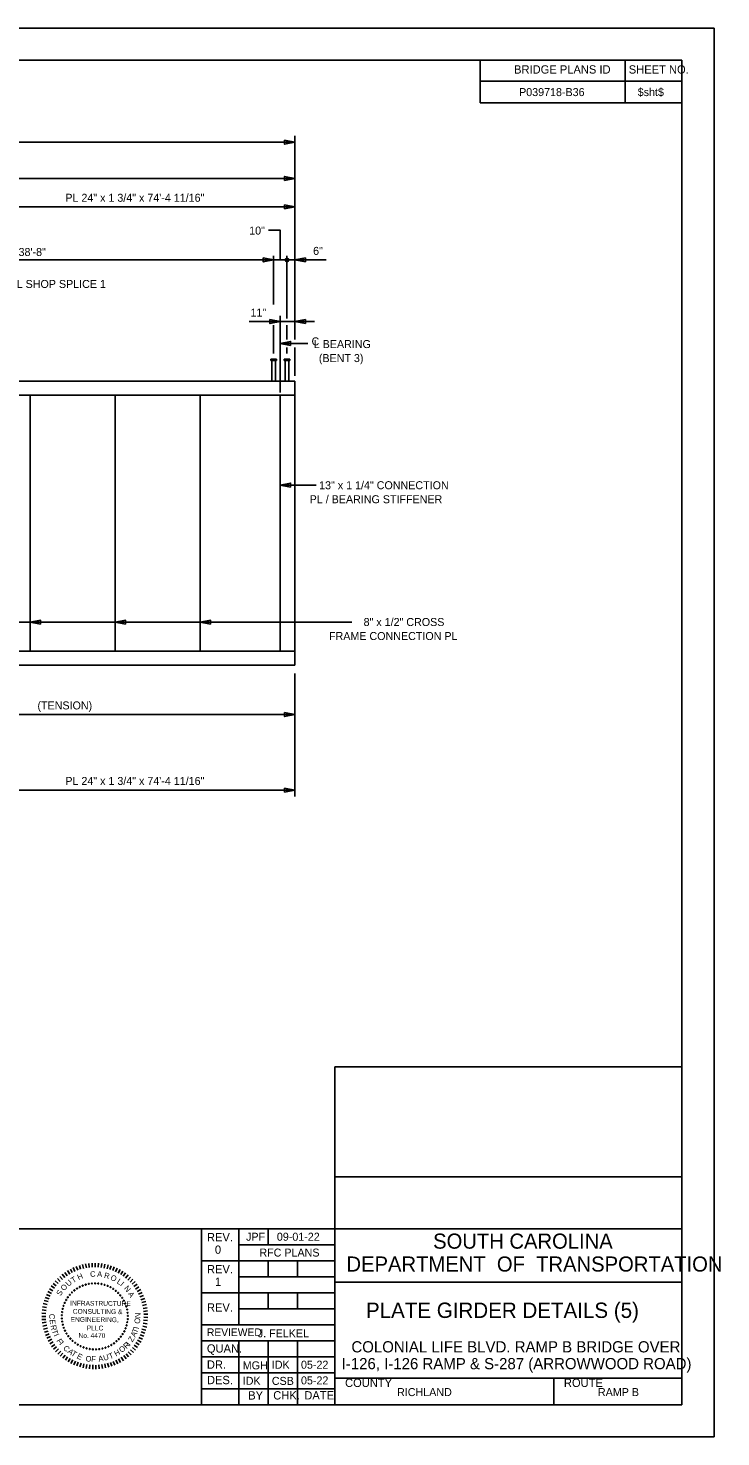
# Model space of a CAD drawing. Extents: x -305 to -161, y -187 to -99.
# Drawn here: x -204 to -160.8, y -187.5 to -99.5 of the extents above; entities that cross this region are included whole.
import ezdxf

# ---------------------------------------------------------------- set-up
doc = ezdxf.new("R2010")
doc.units = 0
for name, color, linetype in [('BR_AUTO DIMENSION', 7, 'Continuous'), ('BR_BORDER LINES', 7, 'Continuous'), ('BR_CENTER LINES', 7, 'Continuous'), ('BR_STRUCTURAL STEEL', 7, 'Continuous'), ('BR_TEXT', 7, 'Continuous'), ('Default', 7, 'Continuous'), ('Level 31', 7, 'Continuous')]:
    doc.layers.add(name, color=color, linetype=linetype)

msp = doc.modelspace()

# ---------------------------------------------------------------- linework, layer by layer
at = {"layer": 'BR_AUTO DIMENSION'}
for p, q in [((-187.347, -118.929), (-187.347, -106.206)), ((-284.433, -106.618), (-187.347, -106.618)), ((-227.882, -108.876), (-187.347, -108.876)), ((-187.347, -110.653), (-206.632, -110.653)), ((-223.034, -113.971), (-188.68, -113.971)), ((-188.68, -116.751), (-188.68, -113.71)), ((-185.394, -113.971), (-188.68, -113.971)), ((-187.847, -117.621), (-187.847, -113.71)), ((-190.196, -117.821), (-186.124, -117.821)), ((-188.68, -119.81), (-188.68, -118.048)), ((-187.847, -118.929), (-187.847, -118.048)), ((-188.264, -119.183), (-186.541, -119.183)), ((-187.847, -119.81), (-187.847, -119.447)), ((-187.347, -121.218), (-187.347, -119.447)), ((-188.264, -128.037), (-186.017, -128.037)), ((-219.809, -136.601), (-183.797, -136.601)), ((-187.347, -139.795), (-187.347, -147.486)), ((-187.347, -142.367), (-216.132, -142.367)), ((-206.632, -147.085), (-187.347, -147.085))]:
    msp.add_line(p, q, dxfattribs=at)
for points in [[(-187.997, -106.493), (-187.347, -106.618), (-187.997, -106.743)], [(-187.997, -109.001), (-187.347, -108.876), (-187.997, -108.751)], [(-187.997, -110.778), (-187.347, -110.653), (-187.997, -110.528)], [(-189.33, -113.846), (-188.68, -113.971), (-189.33, -114.096)], [(-186.697, -114.096), (-187.347, -113.971), (-186.697, -113.846)], [(-188.914, -117.696), (-188.264, -117.821), (-188.914, -117.946)], [(-186.697, -117.946), (-187.347, -117.821), (-186.697, -117.696)], [(-187.614, -119.308), (-188.264, -119.183), (-187.614, -119.058)], [(-187.614, -128.162), (-188.264, -128.037), (-187.614, -127.912)], [(-203.23, -136.726), (-203.88, -136.601), (-203.23, -136.476)], [(-197.921, -136.726), (-198.571, -136.601), (-197.921, -136.476)], [(-192.611, -136.726), (-193.261, -136.601), (-192.611, -136.476)], [(-187.997, -142.242), (-187.347, -142.367), (-187.997, -142.492)], [(-187.997, -146.96), (-187.347, -147.085), (-187.997, -147.21)]]:
    msp.add_lwpolyline(points, close=True, dxfattribs=at)
msp.add_lwpolyline([(-188.264, -113.971), (-188.264, -112.117), (-189.004, -112.117)], dxfattribs=at)
msp.add_circle((-187.847, -113.971), 0.111, dxfattribs=at)
at = {"layer": 'BR_BORDER LINES'}
for p, q in [((-163.178, -101.489), (-297.843, -101.489)), ((-175.788, -104.156), (-175.788, -101.489)), ((-166.722, -104.156), (-166.722, -101.489)), ((-163.178, -185.489), (-163.178, -101.489)), ((-175.788, -102.808), (-163.178, -102.808)), ((-166.722, -102.808), (-163.178, -102.808)), ((-163.178, -104.156), (-175.788, -104.156)), ((-184.846, -185.489), (-184.846, -164.383)), ((-184.846, -164.383), (-163.178, -164.383)), ((-184.845, -171.242), (-163.178, -171.242)), ((-214.64, -174.489), (-193.18, -174.489)), ((-193.18, -185.489), (-193.18, -174.489)), ((-193.18, -174.489), (-163.178, -174.489)), ((-190.846, -174.489), (-190.846, -180.489)), ((-189.013, -175.489), (-189.013, -174.489)), ((-190.846, -175.489), (-184.846, -175.489)), ((-193.18, -176.489), (-184.846, -176.489)), ((-189.013, -177.489), (-189.013, -176.489)), ((-187.179, -177.489), (-187.179, -176.489)), ((-190.846, -177.489), (-184.846, -177.489)), ((-193.18, -178.489), (-184.846, -178.489)), ((-189.013, -179.489), (-189.013, -178.489)), ((-187.179, -179.489), (-187.179, -178.489)), ((-184.846, -177.822), (-184.846, -177.822)), ((-184.846, -177.823), (-163.178, -177.823)), ((-190.846, -179.489), (-184.846, -179.489)), ((-193.18, -180.489), (-184.846, -180.489)), ((-193.18, -181.489), (-184.846, -181.489)), ((-190.846, -181.489), (-190.846, -185.489)), ((-189.013, -181.489), (-189.013, -185.489)), ((-187.179, -181.489), (-187.179, -185.489)), ((-193.18, -182.489), (-184.846, -182.489)), ((-193.18, -183.489), (-184.846, -183.489)), ((-184.846, -183.823), (-163.178, -183.823)), ((-184.456, -183.823), (-163.178, -183.823)), ((-171.179, -185.489), (-171.179, -183.823)), ((-193.18, -184.489), (-184.846, -184.489)), ((-297.843, -185.489), (-163.178, -185.489))]:
    msp.add_line(p, q, dxfattribs=at)
at = {"layer": 'BR_CENTER LINES'}
msp.add_line((-188.264, -117.463), (-188.264, -122.256), dxfattribs=at)
at = {"layer": 'BR_STRUCTURAL STEEL'}
for p, q in [((-187.347, -121.537), (-206.632, -121.537)), ((-187.347, -121.537), (-187.347, -122.412)), ((-187.347, -122.412), (-284.433, -122.412)), ((-203.88, -138.412), (-203.88, -122.412)), ((-198.571, -138.412), (-198.571, -122.412)), ((-193.261, -138.412), (-193.261, -122.412)), ((-188.264, -122.412), (-188.264, -138.412)), ((-187.347, -122.412), (-187.347, -138.412)), ((-187.347, -138.412), (-284.433, -138.412)), ((-187.347, -139.287), (-187.347, -138.412)), ((-187.347, -139.287), (-206.632, -139.287))]:
    msp.add_line(p, q, dxfattribs=at)
at = {"layer": 'BR_TEXT'}
for p, q in [((-201.001, -176.844), (-200.912, -177.082)), ((-200.81, -176.779), (-200.735, -177.023)), ((-200.615, -176.726), (-200.555, -176.974)), ((-200.417, -176.685), (-200.373, -176.936)), ((-200.217, -176.656), (-200.188, -176.909)), ((-200.016, -176.64), (-200.002, -176.894)), ((-199.814, -176.636), (-199.816, -176.89)), ((-199.612, -176.644), (-199.63, -176.898)), ((-199.411, -176.664), (-199.444, -176.917)), ((-199.212, -176.697), (-199.26, -176.947)), ((-199.015, -176.741), (-199.079, -176.988)), ((-198.821, -176.798), (-198.9, -177.04)), ((-198.631, -176.866), (-198.724, -177.103)), ((-202.321, -177.748), (-202.13, -177.917)), ((-202.182, -177.601), (-202.002, -177.781)), ((-202.035, -177.463), (-201.866, -177.654)), ((-201.879, -177.334), (-201.723, -177.535)), ((-201.716, -177.215), (-201.572, -177.425)), ((-201.546, -177.106), (-201.415, -177.324)), ((-201.37, -177.007), (-201.252, -177.233)), ((-201.188, -176.92), (-201.084, -177.153)), ((-198.446, -176.946), (-198.553, -177.177)), ((-198.265, -177.037), (-198.387, -177.261)), ((-198.091, -177.139), (-198.226, -177.355)), ((-197.923, -177.251), (-198.071, -177.458)), ((-197.762, -177.373), (-197.922, -177.571)), ((-197.609, -177.505), (-197.781, -177.693)), ((-197.464, -177.646), (-197.647, -177.823)), ((-202.867, -178.593), (-202.634, -178.696)), ((-202.779, -178.411), (-202.553, -178.529)), ((-202.679, -178.235), (-202.461, -178.366)), ((-202.57, -178.065), (-202.36, -178.21)), ((-202.45, -177.903), (-202.25, -178.06)), ((-197.329, -177.795), (-197.522, -177.961)), ((-197.202, -177.952), (-197.405, -178.106)), ((-197.086, -178.117), (-197.298, -178.258)), ((-196.979, -178.289), (-197.199, -178.417)), ((-196.883, -178.467), (-197.111, -178.581)), ((-203.104, -179.363), (-202.853, -179.407)), ((-203.063, -179.165), (-202.815, -179.225)), ((-203.009, -178.97), (-202.766, -179.045)), ((-202.944, -178.779), (-202.705, -178.869)), ((-196.799, -178.65), (-197.033, -178.75)), ((-196.725, -178.838), (-196.965, -178.924)), ((-196.664, -179.03), (-196.908, -179.101)), ((-196.614, -179.226), (-196.862, -179.282)), ((-196.576, -179.424), (-196.827, -179.465)), ((-203.156, -179.965), (-202.901, -179.964)), ((-203.151, -179.764), (-202.897, -179.777)), ((-203.149, -180.167), (-202.895, -180.15)), ((-203.134, -179.562), (-202.881, -179.592)), ((-203.129, -180.368), (-202.877, -180.335)), ((-196.57, -180.43), (-196.822, -180.393)), ((-196.55, -179.625), (-196.804, -179.65)), ((-196.547, -180.23), (-196.8, -180.208)), ((-196.537, -179.826), (-196.791, -179.836)), ((-196.535, -180.028), (-196.79, -180.022)), ((-203.097, -180.568), (-202.847, -180.52)), ((-203.053, -180.765), (-202.807, -180.701)), ((-202.997, -180.959), (-202.755, -180.881)), ((-202.93, -181.149), (-202.693, -181.056)), ((-202.851, -181.335), (-202.62, -181.228)), ((-196.784, -181.207), (-197.02, -181.111)), ((-196.713, -181.018), (-196.954, -180.936)), ((-196.653, -180.825), (-196.899, -180.758)), ((-196.606, -180.629), (-196.855, -180.577)), ((-202.761, -181.516), (-202.536, -181.395)), ((-202.66, -181.69), (-202.443, -181.556)), ((-202.548, -181.859), (-202.34, -181.711)), ((-202.426, -182.02), (-202.228, -181.86)), ((-202.295, -182.173), (-202.107, -182.002)), ((-202.155, -182.319), (-201.977, -182.136)), ((-197.438, -182.219), (-197.623, -182.045)), ((-197.304, -182.068), (-197.5, -181.905)), ((-197.179, -181.91), (-197.385, -181.759)), ((-197.065, -181.743), (-197.279, -181.605)), ((-196.96, -181.57), (-197.182, -181.446)), ((-196.867, -181.392), (-197.096, -181.281)), ((-202.006, -182.455), (-201.84, -182.262)), ((-201.849, -182.582), (-201.695, -182.379)), ((-201.685, -182.699), (-201.543, -182.487)), ((-201.513, -182.806), (-201.385, -182.586)), ((-201.336, -182.903), (-201.221, -182.675)), ((-201.153, -182.988), (-201.053, -182.754)), ((-200.965, -183.062), (-200.879, -182.822)), ((-200.773, -183.125), (-200.702, -182.88)), ((-200.577, -183.175), (-200.521, -182.927)), ((-200.379, -183.214), (-200.338, -182.962)), ((-200.179, -183.24), (-200.154, -182.987)), ((-199.978, -183.254), (-199.968, -183)), ((-199.776, -183.256), (-199.781, -183.002)), ((-199.574, -183.246), (-199.595, -182.992)), ((-199.373, -183.223), (-199.41, -182.971)), ((-199.174, -183.188), (-199.226, -182.939)), ((-198.978, -183.142), (-199.045, -182.896)), ((-198.785, -183.083), (-198.867, -182.842)), ((-198.596, -183.012), (-198.692, -182.777)), ((-198.411, -182.93), (-198.522, -182.701)), ((-198.232, -182.837), (-198.356, -182.615)), ((-198.059, -182.734), (-198.196, -182.519)), ((-197.892, -182.62), (-198.042, -182.414)), ((-197.733, -182.495), (-197.895, -182.3)), ((-197.581, -182.362), (-197.756, -182.176))]:
    msp.add_line(p, q, dxfattribs=at)
for centre, start, end in [((-201.408, -178.617), 49.37299, 229.37299), ((-201.408, -178.617), 229.37299, 49.37299), ((-201.27, -178.472), 43.83453, 223.83453), ((-201.27, -178.472), 223.83453, 43.83453), ((-201.12, -178.341), 38.29606, 218.29606), ((-201.12, -178.341), 218.29606, 38.29606), ((-200.957, -178.226), 32.7576, 212.7576), ((-200.957, -178.226), 212.7576, 32.7576), ((-200.785, -178.127), 27.21914, 207.21914), ((-200.785, -178.127), 207.21914, 27.21914), ((-200.603, -178.045), 21.68068, 201.68068), ((-200.603, -178.045), 201.68068, 21.68068), ((-200.414, -177.98), 16.14222, 196.14222), ((-200.414, -177.98), 196.14222, 16.14222), ((-200.22, -177.935), 10.60376, 190.60376), ((-200.22, -177.935), 190.60376, 10.60376), ((-200.023, -177.908), 5.06529, 185.06529), ((-200.023, -177.908), 185.06529, 5.06529), ((-199.824, -177.9), 359.52683, 179.52683), ((-199.824, -177.9), 179.52683, 359.52683), ((-199.625, -177.912), 353.98837, 173.98837), ((-199.625, -177.912), 173.98837, 353.98837), ((-199.428, -177.943), 168.44991, 348.44991), ((-199.428, -177.943), 348.44991, 168.44991), ((-199.235, -177.992), 162.91145, 342.91145), ((-199.235, -177.992), 342.91145, 162.91145), ((-199.047, -178.06), 157.37299, 337.37299), ((-199.047, -178.06), 337.37299, 157.37299), ((-198.867, -178.146), 151.83453, 331.83453), ((-198.867, -178.146), 331.83453, 151.83453), ((-198.697, -178.249), 146.29606, 326.29606), ((-198.697, -178.249), 326.29606, 146.29606), ((-198.537, -178.368), 140.7576, 320.7576), ((-198.537, -178.368), 320.7576, 140.7576), ((-198.389, -178.502), 135.21914, 315.21914), ((-198.389, -178.502), 315.21914, 135.21914), ((-198.255, -178.649), 129.68068, 309.68068), ((-198.255, -178.649), 309.68068, 129.68068), ((-201.854, -179.497), 77.06529, 257.06529), ((-201.854, -179.497), 257.06529, 77.06529), ((-201.8, -179.305), 71.52683, 251.52683), ((-201.8, -179.305), 251.52683, 71.52683), ((-201.727, -179.12), 65.98837, 245.98837), ((-201.727, -179.12), 245.98837, 65.98837), ((-201.637, -178.942), 60.44991, 240.44991), ((-201.637, -178.942), 240.44991, 60.44991), ((-201.53, -178.774), 54.91145, 234.91145), ((-201.53, -178.774), 234.91145, 54.91145), ((-198.135, -178.809), 124.14222, 304.14222), ((-198.135, -178.809), 304.14222, 124.14222), ((-198.032, -178.979), 118.60376, 298.60376), ((-198.032, -178.979), 298.60376, 118.60376), ((-197.945, -179.159), 113.06529, 293.06529), ((-197.945, -179.159), 293.06529, 113.06529), ((-197.876, -179.346), 107.52683, 287.52683), ((-197.876, -179.346), 287.52683, 107.52683), ((-197.826, -179.538), 101.98837, 281.98837), ((-197.826, -179.538), 281.98837, 101.98837), ((-201.906, -179.892), 88.14222, 268.14222), ((-201.904, -180.091), 93.68068, 273.68068), ((-201.89, -179.693), 82.60376, 262.60376), ((-201.882, -180.289), 99.21914, 279.21914), ((-201.906, -179.892), 268.14222, 88.14222), ((-201.904, -180.091), 273.68068, 93.68068), ((-201.89, -179.693), 262.60376, 82.60376), ((-201.882, -180.289), 279.21914, 99.21914), ((-197.815, -180.331), 79.83453, 259.83453), ((-197.795, -179.735), 96.44991, 276.44991), ((-197.815, -180.331), 259.83453, 79.83453), ((-197.789, -180.133), 85.37299, 265.37299), ((-197.782, -179.934), 90.91145, 270.91145), ((-197.795, -179.735), 276.44991, 96.44991), ((-197.789, -180.133), 265.37299, 85.37299), ((-197.782, -179.934), 270.91145, 90.91145), ((-201.841, -180.484), 104.7576, 284.7576), ((-201.841, -180.484), 284.7576, 104.7576), ((-201.781, -180.675), 110.29606, 290.29606), ((-201.781, -180.675), 290.29606, 110.29606), ((-201.703, -180.858), 115.83453, 295.83453), ((-201.703, -180.858), 295.83453, 115.83453), ((-201.608, -181.033), 121.37299, 301.37299), ((-201.608, -181.033), 301.37299, 121.37299), ((-201.497, -181.199), 126.91145, 306.91145), ((-201.497, -181.199), 306.91145, 126.91145), ((-198.219, -181.232), 52.14222, 232.14222), ((-198.219, -181.232), 232.14222, 52.14222), ((-198.104, -181.069), 57.68068, 237.68068), ((-198.104, -181.069), 237.68068, 57.68068), ((-198.005, -180.896), 63.21914, 243.21914), ((-198.005, -180.896), 243.21914, 63.21914), ((-197.924, -180.714), 68.7576, 248.7576), ((-197.924, -180.714), 248.7576, 68.7576), ((-197.86, -180.525), 74.29606, 254.29606), ((-197.86, -180.525), 254.29606, 74.29606), ((-201.37, -181.352), 132.44991, 312.44991), ((-201.37, -181.352), 312.44991, 132.44991), ((-201.228, -181.493), 137.98837, 317.98837), ((-201.228, -181.493), 317.98837, 137.98837), ((-201.074, -181.619), 143.52683, 323.52683), ((-201.074, -181.619), 323.52683, 143.52683), ((-200.909, -181.73), 149.06529, 329.06529), ((-200.909, -181.73), 329.06529, 149.06529), ((-200.733, -181.825), 154.60376, 334.60376), ((-200.733, -181.825), 334.60376, 154.60376), ((-200.549, -181.902), 160.14222, 340.14222), ((-200.549, -181.902), 340.14222, 160.14222), ((-200.359, -181.961), 165.68068, 345.68068), ((-200.359, -181.961), 345.68068, 165.68068), ((-200.164, -182.001), 171.21914, 351.21914), ((-200.164, -182.001), 351.21914, 171.21914), ((-199.965, -182.022), 176.7576, 356.7576), ((-199.965, -182.022), 356.7576, 176.7576), ((-199.766, -182.024), 2.29606, 182.29606), ((-199.766, -182.024), 182.29606, 2.29606), ((-199.568, -182.007), 7.83453, 187.83453), ((-199.568, -182.007), 187.83453, 7.83453), ((-199.372, -181.971), 13.37299, 193.37299), ((-199.372, -181.971), 193.37299, 13.37299), ((-199.18, -181.916), 18.91145, 198.91145), ((-199.18, -181.916), 198.91145, 18.91145), ((-198.995, -181.842), 24.44991, 204.44991), ((-198.995, -181.842), 204.44991, 24.44991), ((-198.817, -181.752), 29.98837, 209.98837), ((-198.817, -181.752), 209.98837, 29.98837), ((-198.649, -181.644), 35.52683, 215.52683), ((-198.649, -181.644), 215.52683, 35.52683), ((-198.493, -181.521), 41.06529, 221.06529), ((-198.493, -181.521), 221.06529, 41.06529), ((-198.349, -181.383), 46.60376, 226.60376), ((-198.349, -181.383), 226.60376, 46.60376)]:
    msp.add_arc(centre, 0.028, start, end, dxfattribs=at)
at = {"layer": 'Default'}
for p, q in [((-188.852, -120.162), (-188.852, -120.256)), ((-188.852, -120.162), (-188.508, -120.162)), ((-188.852, -120.256), (-188.508, -120.256)), ((-188.79, -120.256), (-188.79, -121.537)), ((-188.571, -120.256), (-188.571, -121.537)), ((-188.508, -120.162), (-188.508, -120.256)), ((-188.019, -120.162), (-188.019, -120.256)), ((-188.019, -120.162), (-187.675, -120.162)), ((-188.019, -120.256), (-187.675, -120.256)), ((-187.956, -120.256), (-187.956, -121.537)), ((-187.738, -120.256), (-187.738, -121.537)), ((-187.675, -120.162), (-187.675, -120.256))]:
    msp.add_line(p, q, dxfattribs=at)
at = {"layer": 'Level 31'}
msp.add_line((-174.011, -179.583), (-174.011, -179.583), dxfattribs=at)
msp.add_lwpolyline([(-305.176, -187.489), (-161.176, -187.489), (-161.176, -99.489), (-305.176, -99.489)], close=True, dxfattribs=at)

# ---------------------------------------------------------------- texts
at = {"layer": 'BR_AUTO DIMENSION'}
for s, p in [('PL 24" x 1 3/4" x 74\'-4 11/16"', (-201.685, -110.334)), ('10"', (-190.205, -112.385)), ('6"', (-186.212, -113.652)), ('11"', (-190.122, -117.502)), ('(TENSION)', (-203.426, -142.048)), ('PL 24" x 1 3/4" x 74\'-4 11/16"', (-201.685, -146.766))]:
    msp.add_text(s, height=0.5, rotation=360, dxfattribs=at).set_placement(p)
msp.add_text('104 SPA. @ 1\'-4" = 138\'-8"', height=0.5, dxfattribs=at).set_placement((-210.947, -113.721))
at = {"layer": 'BR_TEXT'}
for s, height, p in [('BRIDGE PLANS ID', 0.52, (-173.663, -102.327)), ('SHEET NO.', 0.52, (-166.499, -102.327)), ('P039718-B36', 0.5, (-173.348, -103.732)), ('$sht$', 0.5, (-165.939, -103.732)), ('C', 0.5, (-186.308, -119.306)), ('L BEARING', 0.5, (-186.173, -119.473)), ('(BENT 3)', 0.5, (-185.854, -120.348)), ('13" x 1 1/4" CONNECTION ', 0.5, (-185.836, -128.293)), ('PL / BEARING STIFFENER', 0.5, (-186.428, -129.168)), ('8" x 1/2" CROSS ', 0.5, (-183.058, -136.838)), ('FRAME CONNECTION PL', 0.5, (-185.219, -137.713)), ('REV.', 0.52, (-192.841, -175.277)), ('JPF', 0.5, (-190.4, -175.239)), ('09-01-22', 0.5, (-188.475, -175.239)), ('SOUTH CAROLINA', 0.94348, (-178.718, -175.735)), ('0', 0.52, (-192.345, -176.057)), ('RFC PLANS', 0.5, (-189.566, -176.229)), ('REV.', 0.52, (-192.841, -177.277)), ('DEPARTMENT  OF  TRANSPORTATION', 0.94348, (-184.129, -177.166)), ('1', 0.52, (-192.337, -178.057)), ('REV.', 0.52, (-192.841, -179.667)), ('PLATE GIRDER DETAILS (5)', 0.96, (-182.913, -180.063)), ('REVIEWED', 0.48, (-192.843, -181.195)), ('J. FELKEL', 0.5, (-189.664, -181.272)), ('QUAN.', 0.52, (-192.846, -182.229)), ('COLONIAL LIFE BLVD. RAMP B BRIDGE OVER', 0.7, (-183.82, -182.216)), ('DR.', 0.52, (-192.845, -183.235)), ('MGH', 0.5, (-190.606, -183.274)), ('IDK', 0.5, (-188.79, -183.234)), ('05-22', 0.5, (-186.969, -183.234)), ('I-126, I-126 RAMP & S-287 (ARROWWOOD ROAD) ', 0.7, (-184.429, -183.266)), ('DES.', 0.52, (-192.841, -184.2)), ('IDK', 0.5, (-190.606, -184.24)), ('CSB', 0.5, (-188.79, -184.245)), ('05-22', 0.5, (-186.969, -184.214)), ('COUNTY', 0.52, (-184.217, -184.376)), ('ROUTE', 0.52, (-170.55, -184.376)), ('BY', 0.52, (-190.265, -185.161)), ('CHK.', 0.52, (-188.701, -185.156)), ('DATE', 0.52, (-186.761, -185.156)), ('RICHLAND', 0.5, (-180.968, -184.944)), ('RAMP B', 0.5, (-168.424, -184.944))]:
    msp.add_text(s, height=height, dxfattribs=at).set_placement(p)
for s, height, rotation, p in [('L SHOP SPLICE 1', 0.5, 360, (-204.724, -115.718)), ('U', 0.349, 40.84822, (-201.49, -178.119)), ('T', 0.349, 31.81819, (-201.196, -177.894)), ('H', 0.349, 22.78817, (-200.857, -177.704)), ('C', 0.349, 4.72812, (-200.126, -177.506)), ('A', 0.349, 355.69809, (-199.708, -177.486)), ('R', 0.349, 346.66807, (-199.291, -177.554)), ('O', 0.349, 337.63804, (-198.9, -177.673)), ('L', 0.349, 327.10802, (-198.504, -177.875)), ('S', 0.349, 58.90827, (-201.979, -178.715)), ('O', 0.349, 49.87824, (-201.757, -178.403)), ('I', 0.349, 319.578, (-198.294, -178.026)), ('N', 0.349, 310.54797, (-198.051, -178.23)), ('A', 0.349, 301.51795, (-197.791, -178.559)), ('INFRASTRUCTURE', 0.29909, 359.52683, (-201.385, -179.286)), ('CONSULTING &', 0.29909, 359.52683, (-201.22, -179.8)), ('C', 0.349, 267.02504, (-202.679, -179.795)), ('E', 0.349, 273.02504, (-202.662, -180.161)), ('ENGINEERING,', 0.29909, 359.52683, (-201.354, -180.302)), ('O', 0.349, 83.20849, (-197.038, -180.44)), ('N', 0.349, 89.20849, (-196.993, -180.074)), ('R', 0.349, 279.02504, (-202.61, -180.531)), ('T', 0.349, 285.02504, (-202.541, -180.846)), ('I', 0.349, 293.77127, (-202.422, -181.138)), ('No. 4470', 0.2991, 359.52683, (-200.865, -181.304)), ('PLLC', 0.2991, 359.52683, (-200.347, -180.836)), ('Z', 0.349, 57.39539, (-197.501, -181.594)), ('A', 0.349, 63.39539, (-197.326, -181.288)), ('T', 0.349, 69.39539, (-197.203, -181.047)), ('I', 0.349, 77.90926, (-197.1, -180.777)), ('F', 0.349, 299.77127, (-202.257, -181.482)), ('I', 0.349, 308.52683, (-202.089, -181.698)), ('C', 0.349, 314.52683, (-201.851, -181.978)), ('A', 0.349, 320.52683, (-201.575, -182.213)), ('T', 0.349, 326.52683, (-201.357, -182.366)), ('H', 0.349, 28.52683, (-198.522, -182.478)), ('O', 0.349, 38.52683, (-198.169, -182.254)), ('R', 0.349, 44.52683, (-197.863, -182.014)), ('I', 0.349, 52.33388, (-197.665, -181.825)), ('E', 0.349, 332.52683, (-201.003, -182.558)), ('O', 0.349, 350.52683, (-200.442, -182.753)), ('F', 0.349, 356.52683, (-200.076, -182.79)), ('A', 0.349, 10.52683, (-199.597, -182.796)), ('U', 0.349, 16.52683, (-199.261, -182.742)), ('T', 0.349, 22.52683, (-198.894, -182.645))]:
    msp.add_text(s, height=height, rotation=rotation, dxfattribs=at).set_placement(p)

doc.saveas('drawing.dxf')
